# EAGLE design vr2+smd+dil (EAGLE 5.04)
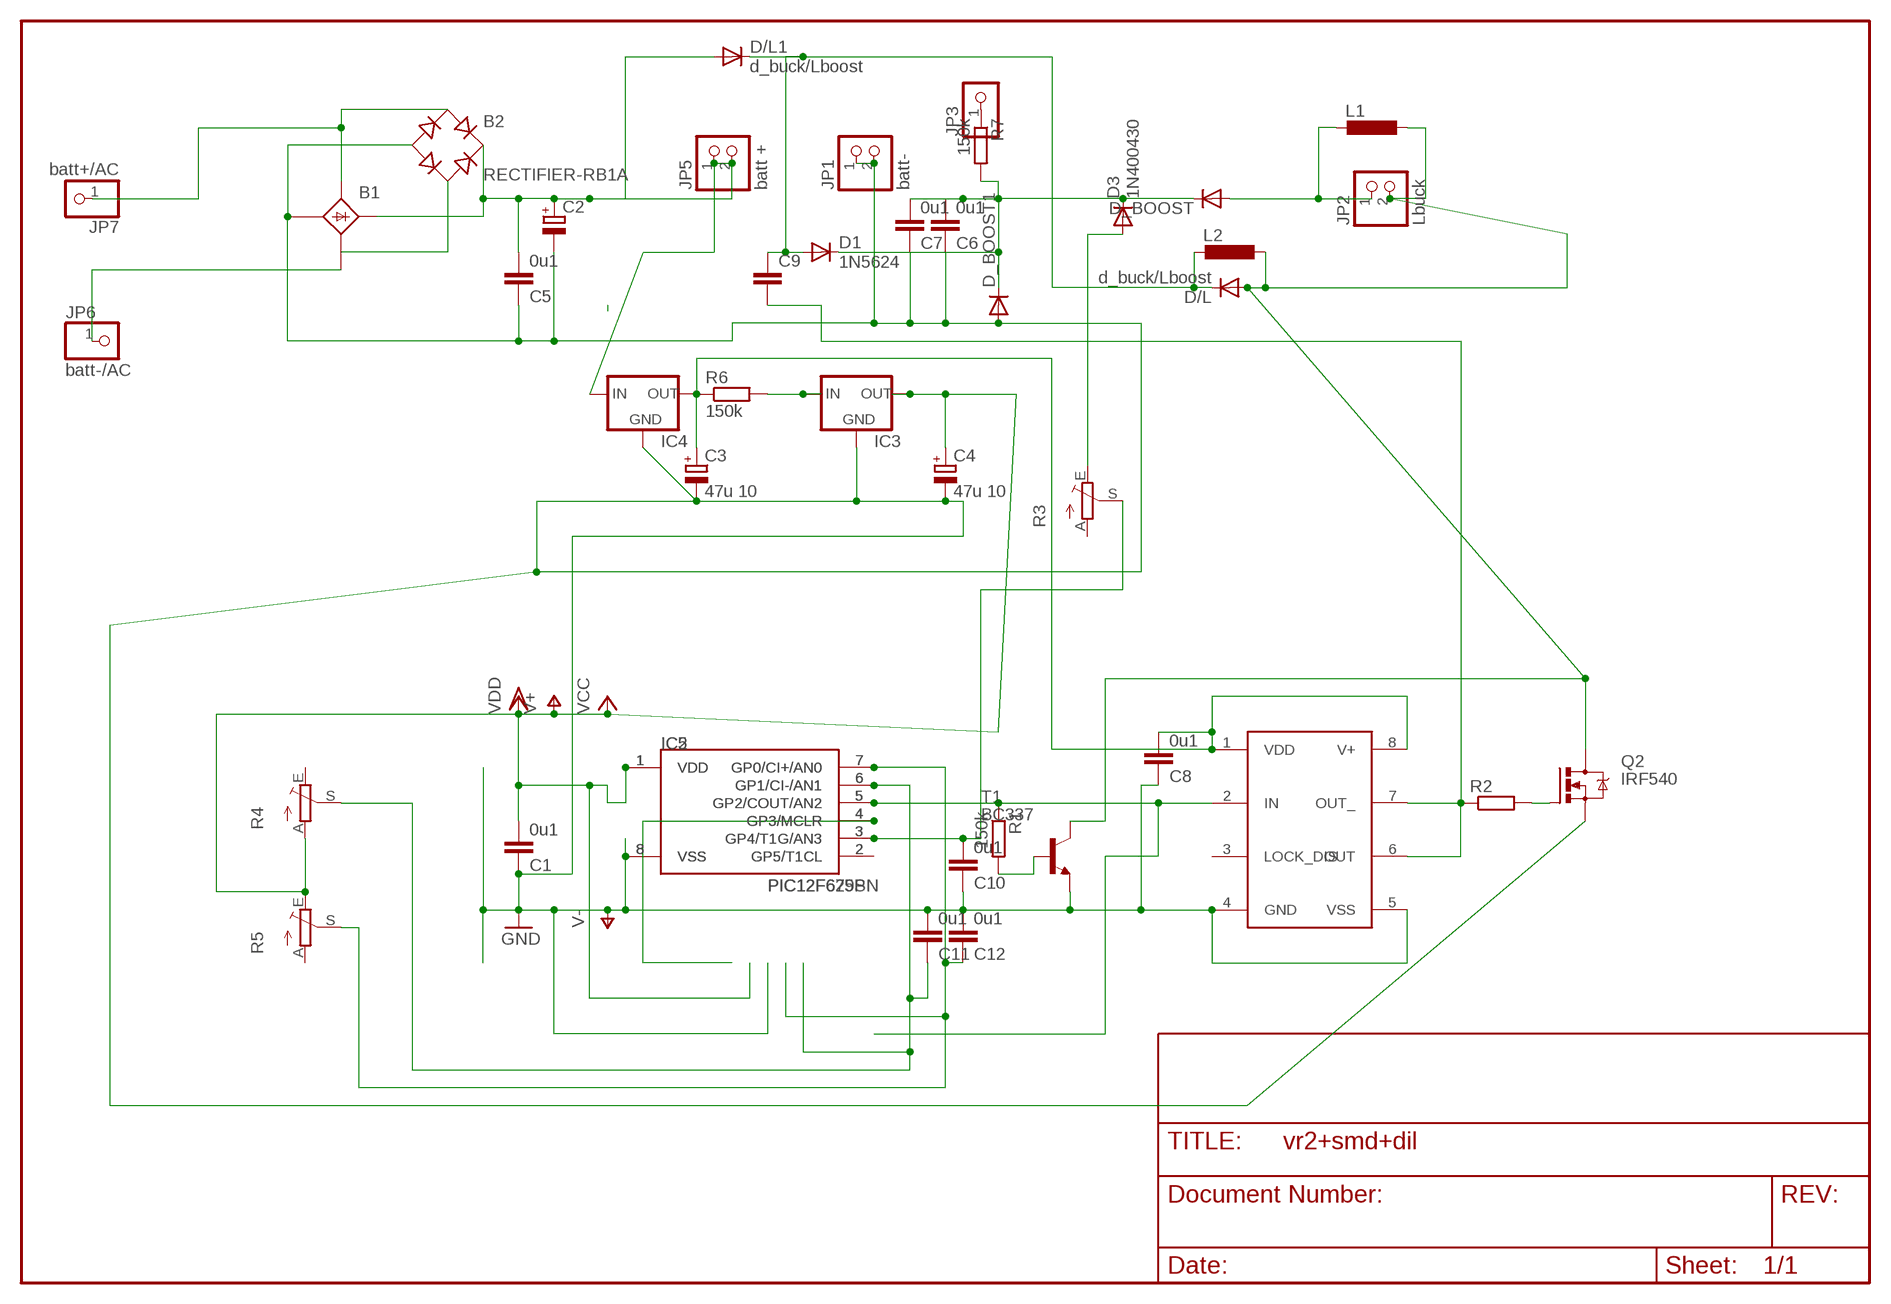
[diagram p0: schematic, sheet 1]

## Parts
B1  B25A-  [B25A-]
B2  RECTIFIER-RB1A  [RB1A]
C1  0u1  C-EUC1206  [C1206]
C2  CPOL-EUE7.5-18  [E7,5-18]
C3  47u 10  CPOL-EUE2,5-6E  [E2,5-6E]
C4  47u 10  CPOL-EUE2.5-6  [E2,5-6]
C5  0u1  C-EUC1206  [C1206]
C6  0u1  C-EUC1206  [C1206]
C7  0u1  C-EUC1206  [C1206]
C8  0u1  C-EUC1206  [C1206]
C9  C-EU050-024X044  [C050-024X044]
C10  0u1  C-EUC1206  [C1206]
C11  0u1  C-EUC1206  [C1206]
C12  0u1  C-EUC1206  [C1206]
D1  1N5624  [DO201-15]
D3  1N400430  [DO41-30]
D/L  d_buck/Lboost  DIODE-C1702-05  [C1702-05]
D/L1  d_buck/Lboost  DIODE-DO201-15  [DO201-15]
D_BOOST  DIODE-DO201-15  [DO201-15]
D_BOOST1  DIODE-DO201-15  [DO201-15]
IC1  TC4432X  [SO-08]
IC2  PIC12F675SN  [SO-08]
IC3  78LXX  [78LXX]
IC4  78LXX  [78LXX]
IC5  PIC12F629P  [DIL8]
JP1  batt-  PINHD-1X2  [1X02]
JP2  Lbuck  PINHD-1X2  [1X02]
JP3  PINHD-1X1  [1X01]
JP5  batt +  PINHD-1X2  [1X02]
JP6  batt-/AC  PINHD-1X1  [1X01]
JP7  batt+/AC  PINHD-1X1  [1X01]
L1  DO3316P  [DO3316P]
L2  DO3316P  [DO3316P]
Q2  IRF540  [TO220BV]
R1  150k  R-EU_0617/17  [0617/17]
R2  R-EU_R1206  [R1206]
R3  TRIM_EU-CA6V  [CA6V]
R4  TRIM_EU-CA6V  [CA6V]
R5  TRIM_EU-CA6V  [CA6V]
R6  150k  R-EU_0204/7  [0204/7]
R7  150k  R-EU_0207/12  [0207/12]
T1  BC337  [TO92]

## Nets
LOAD: C6.2 C7.2 D1.C D3.C D_BOOST1.C D_BOOST.C R7.2
N$1: B1.+ B2.+ C2.+ C5.2 D/L1.A IC4.IN JP5.1 JP5.2
N$2: C9.1 D1.A D/L1.C D/L.C L2.1
N$3: B1.AC2-(AC2) JP6.1
N$4: C3.+ C8.2 IC1.1(VDD) IC1.8(V+) IC4.OUT R6.1
N$5: D_BOOST.A JP2.1 L1.1
N$6: R1.2 T1.2(B)
N$7: C9.2 IC1.6(OUT) IC1.7(OUT_) R2.1
N$8: B1.AC1 B2.AC1 JP7.1
N$9: D/L.A JP2.2 L1.2 L2.2 Q2.D T1.3(C)
N$10: IC2.4(GP3/MCLR) IC5.4(GP3/MCLR)
N$11: B1.AC2 B2.AC2
N$12: C10.2 IC2.3(GP4/T1G/AN3) IC5.3(GP4/T1G/AN3) R3.S
N$13: C12.1 IC2.7(GP0/CI+/AN0) IC5.7(GP0/CI+/AN0) R5.S
N$14: IC1.2(IN) IC2.5(GP2/COUT/AN2) IC5.5(GP2/COUT/AN2) R1.1
N$15: C11.1 IC2.6(GP1/CI-/AN1) IC5.6(GP1/CI-/AN1) R4.S
N$16: D3.A R3.E
N$17: Q2.G R2.2
N$18: IC2.2(GP5/T1CL) IC5.2(GP5/T1CL)
N$19: JP3.1 R7.1
N$20: IC3.IN R6.2
V+: C1.2 C4.+ IC2.1(VDD) IC3.OUT IC5.1(VDD) R4.A R5.E ; supply symbol labelled VCC, VDD
V-: B1.-1(-) B2.- C1.1 C2.- C3.- C4.- C5.1 C6.1 C7.1 C8.1 C10.1 C11.2 C12.2 D_BOOST1.A IC1.4(GND) IC1.5(VSS) IC2.8(VSS) IC3.GND IC4.GND IC5.8(VSS) JP1.1 JP1.2 Q2.S T1.1(E) ; supply symbol labelled GND
Unconnected: B1.+1(+) B1.- B1.AC1-(AC1) IC1.3(LOCK_DIS) R3.A R4.E R5.A

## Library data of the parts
B1 = rectifier:B25A-: RECTIFIER 25-A bridge
B2 = rectifier:RECTIFIER-: Rectifier
C1 C5-C8 C10-C12 = rcl:C-EU: CAPACITOR, European symbol
C2-C4 = rcl:CPOL-EU: POLARIZED CAPACITOR, European symbol
C9 = rcl-2:C-EU: CAPACITOR, European symbol
D1 = diode-1:1N5624: DIODE
D3 = diode-1:1N4004: DIODE
D/L D/L1 D_BOOST D_BOOST1 = diode:DIODE-: DIODE
IC1 = microchip:TC4432
IC2 = microchip-3:PIC12F6*: uPC nW 1k Program Flash memory 2x Timer Comparator 10b A/D converter/ 4xIN
IC3 IC4 = v-reg:78LXX: VOLTAGE REGULATOR
IC5 = microchip-5:PIC12F6*: uPC nW 1k Program Flash memory 2x Timer Comparator 10b A/D converter/ 4xIN
JP1 JP2 JP5 = pinhead:PINHD-1X2: PIN HEADER
JP3 JP6 JP7 = pinhead:PINHD-1X1: PIN HEADER
L1 L2 = inductor-coilcraft:DO3316P: COILCRAFT
Q2 = transistor-power:IRF540: HEXFET Power MOSFET
R1 R6 R7 = rcl:R-EU_: RESISTOR, European symbol
R2 = rcl-2:R-EU_: RESISTOR, European symbol
R3-R5 = pot:TRIM_EU-: POTENTIOMETER
T1 = transistor-neu-to92:BC337: NPN TRANSISTOR

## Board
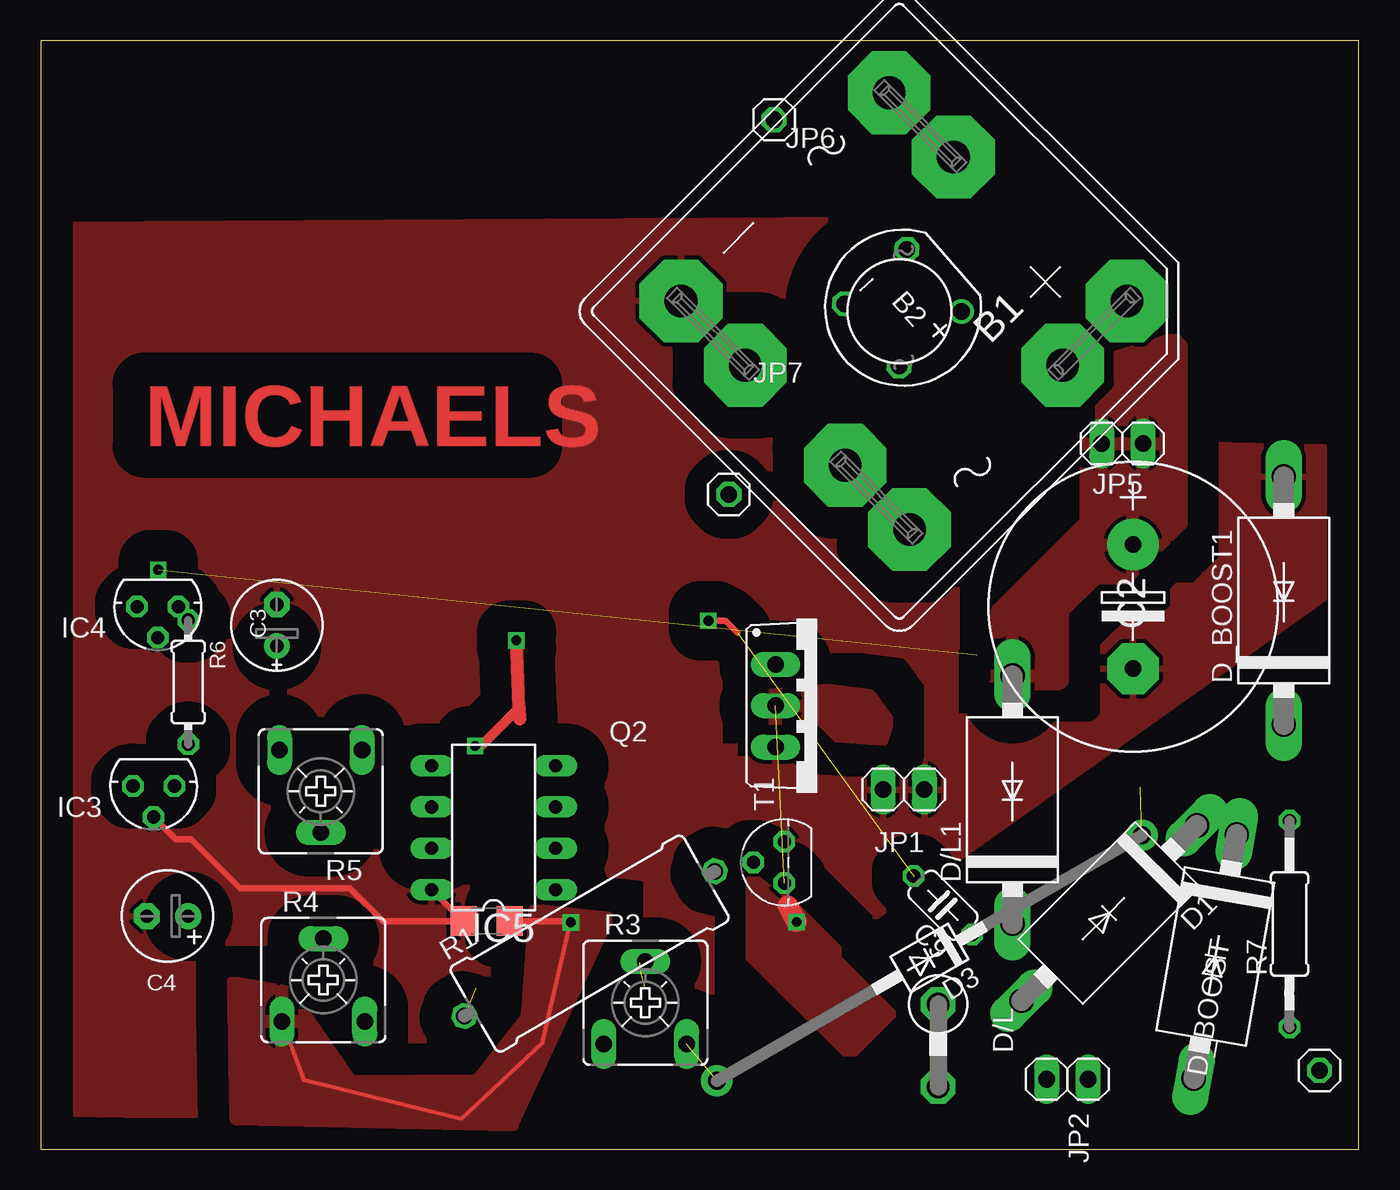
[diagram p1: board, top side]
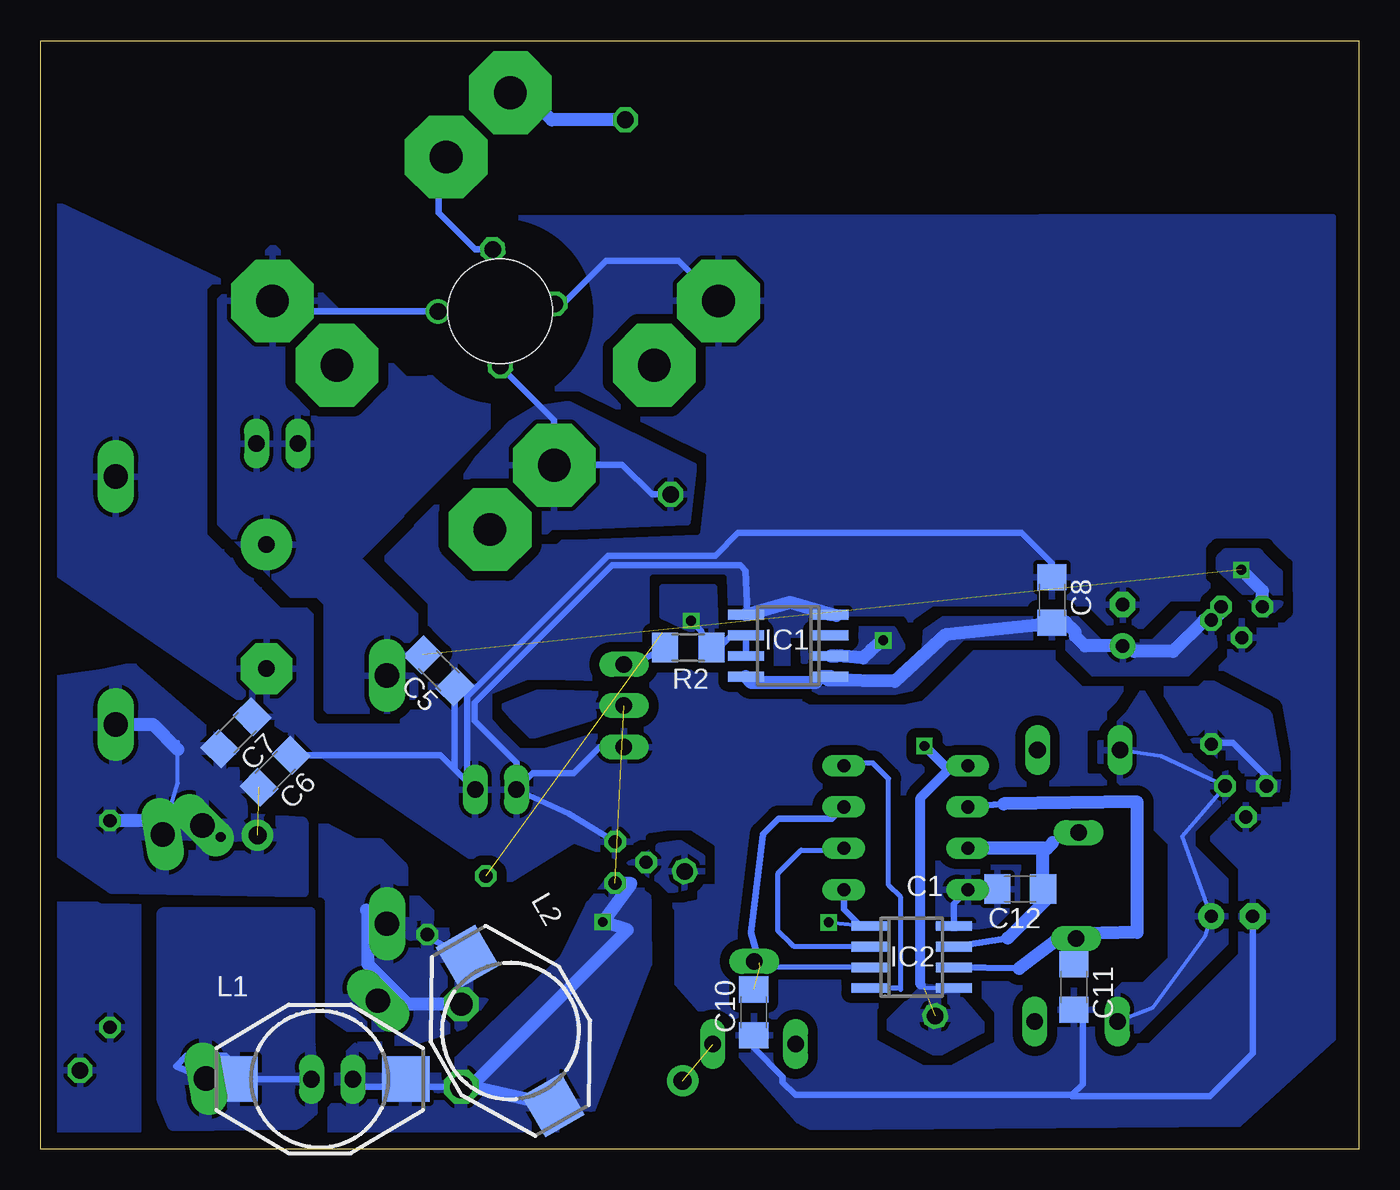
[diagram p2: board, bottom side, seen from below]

Size 81 x 68.09 mm. Coordinates in mm from the lower left corner, seen from the top.
Outline: 0,0 81,0 81,68.09 0,68.09 0,0
Copper layers (1*16): Top 0.035mm / dielectric 1.5mm / Bottom 0.035mm
Design rules "default": minimum track width 10mil, minimum drill 24mil, track to track 8mil, track to pad 8mil, pad to pad 8mil, via to via 8mil, smd to smd 8mil, copper to edge 40mil, drill to drill 8mil, minimum pad ring 10mil, minimum via ring 8mil, stop-mask expansion 4mil, vias tented up to drill 0mil, thermal gap 10mil

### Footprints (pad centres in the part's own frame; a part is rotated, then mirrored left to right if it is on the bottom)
B25A- = drill 2.007 pad 5.08 octagon: + -10.338,9.449; +1 -4.75,9.449; - 9.042,-4.343; -1 9.042,-9.931; AC1 9.042,4.343; AC1- 9.042,9.931; AC2 -9.042,-4.343; AC2- -9.042,-9.931 | hole 6.401: 0,0
RB1A = drill 1.016 round: + -2.54,2.54 | drill 1.016 octagon: - 2.54,-2.54; AC1 2.54,2.54; AC2 -2.54,-2.54
C1206 = smd 1.6 x 1.8: 1 -1.4,0; 2 1.4,0
E7,5-18 = drill 1.016 pad 3.15 round: + -3.81,0 | drill 1.016 pad 3.15 octagon: - 3.81,0
E2,5-6E = drill 0.813 pad 1.575 round: + -1.27,0 | drill 0.813 pad 1.575 octagon: - 1.27,0
E2,5-6 = drill 0.813 pad 1.6 round: + -1.27,0 | drill 0.813 pad 1.6 octagon: - 1.27,0
C050-024X044 = drill 0.813 octagon: 1 -2.54,0; 2 2.54,0
DO201-15 = drill 1.499 long: A 7.62,0; C -7.62,0
DO41-30 = drill 1.118 pad 1.93 round: A 15.08,0; C -15.08,0
C1702-05 = drill 1.397 octagon: A 2.54,0; C -2.54,0
SO-08 = smd 0.6 x 2.2: 1 -1.905,-2.6; 2 -0.635,-2.6; 3 0.635,-2.6; 4 1.905,-2.6; 5 1.905,2.6; 6 0.635,2.6; 7 -0.635,2.6; 8 -1.905,2.6
78LXX = drill 0.813 octagon: GND 0,1.905; IN 1.27,0; OUT -1.27,0
DIL8 = drill 0.813 long: 1 -3.81,-3.81; 2 -1.27,-3.81; 3 1.27,-3.81; 4 3.81,-3.81; 5 3.81,3.81; 6 1.27,3.81; 7 -1.27,3.81; 8 -3.81,3.81
1X02 = drill 1.016 long: 1 -1.27,0; 2 1.27,0
1X01 = drill 1.016 octagon: 1 0,0
DO3316P = smd 2.92 x 2.79: 1 -5.28,0; 2 5.28,0
TO220BV = drill 1.016 long: D 0,-2.54; G -2.54,-2.54; S 2.54,-2.54
0617/17 = drill 1.016 octagon: 1 -8.89,0; 2 8.89,0
R1206 = smd 1.6 x 1.803: 1 -1.422,0; 2 1.422,0
CA6V = drill 1.016 long: A -2.54,-2.54; E 2.54,-2.54; S 0,2.54
0204/7 = drill 0.813 octagon: 1 -3.81,0; 2 3.81,0
0207/12 = drill 0.813 octagon: 1 -6.35,0; 2 6.35,0
TO92 = drill 0.813 octagon: 1 1.27,0; 2 0,1.905; 3 -1.27,0

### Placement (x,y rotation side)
B1  52.76,51.47 225 top
B2  52.99,51.69 221.3 top
C1  27.4,14.01 0 top
C2  67.13,33.32 270 top
C3  14.51,32.18 90 top
C4  7.79,14.31 180 top
C5  56.54,29.38 135 bottom
C6  66.59,23.21 225 bottom
C7  68.99,25.58 225 bottom
C8  18.86,33.73 270 bottom
C9  55.44,14.98 135 top
C10  37.18,8.41 90 bottom
C11  17.51,9.97 270 bottom
C12  20.8,15.98 180 bottom
D1  65.66,14.5 225 top
D3  54.61,11.74 210 top
D/L  55.15,6.36 270 top
D/L1  59.72,21.46 90 top
D_BOOST  72.18,11.83 260 top
D_BOOST1  76.39,33.69 90 top
IC1  35.06,30.92 90 bottom
IC2  27.48,11.8 270 bottom
IC3  6.94,22.3 180 top
IC4  7.2,33.32 180 top
IC5  27.84,19.75 90 top
JP1  53.03,22.09 180 top
JP2  63.09,4.29 180 top
JP3  78.58,4.84 0 top
JP5  66.47,43.35 180 top
JP6  45.07,63.23 0 top
JP7  42.29,40.22 0 top
L1  63.85,4.31 0 bottom
L2  52.14,7.26 300 bottom
Q2  47.7,27.24 270 top
R1  33.73,12.62 30 top
R2  41.21,30.81 180 bottom
R3  37.16,8.99 0 top
R4  17.37,10.39 0 top
R5  17.21,21.98 180 top
R6  9.06,28.69 270 top
R7  76.74,13.83 90 top
T1  45.7,17.61 90 top

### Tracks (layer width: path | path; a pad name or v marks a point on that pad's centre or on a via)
LOAD  (via drill 0.6)  (1 unrouted)
  Bottom 0.254: 72.58,25.02 72.58,24.55 72.58,22.48 D_BOOST.C
  Bottom 0.406: 72.7,20.46 72.83,20.59 | 72.7,20.46 D_BOOST.C | v69.94,19.18 71.29,19.05 72.7,20.46
  Bottom 0.813: D_BOOST1.C 74.1,26.07 72.58,24.55 | D_BOOST.C 72.6,20.34 72.58,20.32 72.72,20.18 R7.2
  pour Bottom (isolate 0.61, rank 2): 68.51,20.29 64.94,20.04 64.93,15.84 76.62,16.07 81.04,19.1 81.04,28.59 77.09,29.13 75.4,29.51 69.44,24.38
N$1  (via drill 0.6)  (1 unrouted)
  Top 0.406: JP5.1 67.92,43.18
  Bottom 0.406: B2.+ 65.28,51.46 66.06,52.23 66.62,52.23 B1.+
  Bottom 0.813: IC4.IN 5.93,34.29 v7.22,35.59
  pour Bottom (isolate 0.61): 5.6,33.03 5.04,33.59 5.04,35.32 6.23,36.51 8.12,36.51 8.44,36.2 8.44,35.8
  pour Bottom (isolate 0.61, rank 2): 53.54,49 53.54,44.32 58.86,39 58.86,38.9 61.71,36.06 61.24,36.06 58,32.82 58,27.88 58.95,26.92 63.33,26.92 63.42,27.01 63.42,33.5 63.98,34.06 65.6,34.06 69.97,38.43 69.97,52.18 66.8,55.36 66.66,55.36 58.58,47.28 57.22,47.28 55.85,48.65 55.85,48.78 55.85,49.06 55.44,49.47
  pour Top (isolate 0.61): 69.62,49.81 70.08,49.35 70.08,38.39 66.76,35.08 64.83,35.08 62.79,33.03 62.79,28.79 62.56,28.56 58.68,28.56 58.8,28.68 58.8,33.13 64.26,38.6 64.26,48.09
N$2
  Bottom 0.406: L2.1 57.24,13.03 C9.1
  Bottom 0.813: D/L.C 58.42,8.9 60.88,11.37 60.88,14.57 60.99,14.68 D/L1.C
  pour Bottom (isolate 0.61, rank 3): 53.36,11.19 53.63,9.65 55,7.75 59.95,6.12 64.45,9.22 64.32,20.07 61.73,18.72 60.22,18.72 58.82,17.32 58.82,16.14 54.73,12.05
N$3
  Bottom 0.813: JP6.1 49.6,63.23 51.95,65.58 51.95,64.49 51.67,64.21 51.69,64.21 52.13,64.66 B1.AC2-
N$4
  Bottom 0.813: IC1.8 37.66,29 37.32,28.66 33.38,28.66 33.03,29.02 IC1.1 32.61,28.8 28.52,28.74 25.41,31.59 18.02,32.37 17.42,31.77 17.42,31.51 16.82,30.91 C3.+ 14.13,30.91 13.8,30.58 11.43,30.58 9.51,32.5 R6.1 8.99,32.44 8.47,32.96 IC4.OUT
  pour Bottom (isolate 0.61, rank 2): 9.15,32.87 10.89,32.87 12.63,31.13 15.88,31.13 17.31,32.55 25.5,32.59 26.62,31.81 26.72,29.86 29.33,29.34 33.51,29.39 33.51,28.28 33.16,28.11 28.5,28.11 27.5,28.31 27.12,28.66 24.34,31.45 18.17,31.45 17.85,31.13 17.85,30.72 16.35,29.22 10.5,29.22 8.84,30.89
N$5
  Bottom 0.406: JP2.1 68.21,4.29 69.64,5.73 72.04,5.73 72.67,5.11 D_BOOST.A
  pour Bottom (isolate 0.61): 64.31,4.23 64.5,6.5 64.5,14.5 73.5,14.45 73.5,3.07 72.84,1.51 65.27,1.6 64.27,2.45
N$6
  pour Bottom (isolate 0.61): 44.8,17.54 43.14,18.44 42.96,18.64 41.72,18.83 40.36,17.96 40.36,16.78 41.39,16.09 42.34,15.88 42.94,16.47
N$7  (via drill 0.6)  (1 unrouted)
  Top 0.406: v41.03,32.46 42.08,32.46 42.82,31.73
  Bottom 0.406: 37.82,30.29 37.87,30.24 | IC1.7 37.82,30.29 | 37.82,30.29 37.66,30.45 IC1.6 38.55,31.56 39.41,30.71 39.92,30.79 R2.1 39.98,30.94 40.42,31.85 v41.03,32.46
  pour Bottom: 40.32,30.59 39.53,32.03 39.63,34.53 42.78,34.53 42.78,32.74 40.32,31.56
N$8
  Bottom 0.406: JP7.1 43.44,40.22 45.27,42.05 49.48,42.05 | 49.48,42.05 50.3,42.05 | 49.48,42.05 B1.AC1 49.44,44.78 B2.AC1
  pour Bottom (isolate 0.61, rank 2): 50.61,45.49 48.56,45.8 40.84,41.99 41.26,38.52 48.03,38.24 49.63,38.24 52.38,35.64 54.98,35.2 56.88,37.11 56.11,39.52 54.12,42.46 52.16,44.55
N$9  (via drill 0.6)  (1 unrouted)
  Top 1.27: v46.45,13.96 45.91,14.96
  Bottom 0.406: 61.98,4.29 61.98,4.46 | 61.98,4.29 JP2.2 | D/L.A 61.98,3.82 61.98,4.29
  Bottom 0.813: 54.58,3.82 D/L.A | 54.58,3.82 44.94,13.46 v46.45,13.96 44.73,16.31 T1.3 | L2.2 54.58,3.82
  pour Bottom (isolate 0.813): 46.03,27.95 50.42,28.07 52.55,27.19 51.75,26.28 50.82,25.35 47.24,26.48 46.39,26.9
  pour Bottom (isolate 0.61, rank 2): 43.86,16.68 46.05,16.33 47.15,14.92 48.73,11.7 56.38,4.33 58.16,4.33 60.02,6.18 61.53,6.18 62.39,5.32 65.74,0.47 65.21,-0.06 48.05,0.51 43.8,11.46
  pour Top: 45.3,15.61 45.79,15.61 49.03,12.37 49.03,11.76 52.44,8.36 52.44,8.24 50.07,5.88 49.36,5.88 43.53,11.71 43.53,16.59 43.76,16.81
  pour Top (isolate 0.61): 44.32,27.65 44.55,27.88 48.31,28.22 50.92,27.88 52.07,26.28 51.72,25.13 48.99,25.36 47.96,26.39 44.21,26.39
N$10
  Bottom 0.305: IC2.4 28.25,9.89 28.15,9.79 28.15,15.47 28.9,16.22 28.9,22.76 29.85,23.71 31.49,23.71 IC5.4
N$11
  Bottom 0.406: B2.AC2 54.32,55.27 56.56,57.52 56.56,60.46 B1.AC2
N$12  (2 unrouted)
  Bottom 0.305: IC2.3 36.79,11.16 R3.S
  Bottom 0.406: 36.84,11.46 37.35,13.28 36.61,19.33 35.66,20.28 32.38,20.28 IC5.3
N$13
  Bottom 0.406: 21.57,12.97 IC2.7 | 19.09,15.43 19.09,15.66 C12.1 | 19.4,18.23 18.8,18.82 18.26,19.37 17.28,19.37 R5.S
  Bottom 0.813: 19.09,15.43 21.57,12.97 | C12.1 19.4,18.23 | IC5.7 19.15,18.48 18.8,18.82
N$14  (via drill 0.6)  (1 unrouted)
  Top 0.61: v26.69,24.77 27.06,24.77 29.41,27.11
  Top 0.813: 29.43,26.42 29.41,27.11 v29.23,31.25
  Bottom 0.254: IC2.5 26.72,9.89 26.93,10.11 | 25.16,23.36 24.23,23.36 IC5.5
  Bottom 0.61: 26.93,10.11 26.93,21.58 25.16,23.36 25.28,23.36 v26.69,24.77
  Bottom 0.813: v29.23,31.25 29.99,30.64 30.46,30.18 32.09,30.3 32.1,30.29 IC1.2
  pour Bottom (isolate 0.61): 30.5,29.44 28.81,29.38 28.06,29.07 28.06,30.98 28.6,31.94 34.19,31.95 34.08,29.95 30.81,29.76
  pour Bottom (isolate 0.61, rank 2): 25.13,9.68 23.25,7.48 25.89,6.05 28.81,7.65 26.67,9.78 26.6,9.78
N$15
  Bottom 0.406: 20.89,11.1 IC2.6 | 21.84,21.21 24.01,21.01 IC5.6 | 17.06,12.93 R4.S 17.37,11.51 C11.1
  Bottom 0.813: 18.14,13.21 13.61,13.32 13.61,21.34 21.84,21.21 | 18.14,13.21 20.89,11.1 | 18.14,13.21 17.06,12.93
N$16  (1 unrouted)
N$17
  Bottom 0.406: Q2.G 45.09,29.78 44.9,29.59 R2.2
N$18
  Bottom 0.305: IC2.2 34.71,12.43 34.88,12.61 34.9,12.61 35.68,13.4 35.68,16.95 34.27,18.36 31.76,18.36 IC5.2
N$19
  pour Bottom (isolate 0.61, rank 3): 75,1.13 81.01,1.22 81.24,3.64 81.24,11.06 80,15 78,15 75,15.05
N$20
  Bottom 0.406: IC3.IN 5.67,22.9 7.73,24.96 8.99,24.96 R6.2
  pour Bottom (isolate 0.61, rank 3): 10.4,25.27 11.9,28.33 9.06,28.42 5.72,26.68 5.09,23.25 5.25,22.02 6.21,22.02
V+  (via drill 0.6)
  Top 0.254: R4.A 16.19,4.25 25.87,1.87 30.83,6.53 v32.57,13.93
  Top 0.406: C1.2 32.5,14.01 v32.57,13.93
  Bottom 0.254: v32.57,13.93 IC2.1 | R4.A 12.63,8.72 9.45,13.08 C4.+ 10.86,19.21 IC3.OUT 12.12,24.13 R5.E
  Bottom 0.406: IC2.1 30.6,13.7 31.64,14.74 IC5.1
  pour Bottom (isolate 0.61): 14.35,6.87 13.97,6.87 8.2,12.64 8.2,16.55 10.23,18.58 10.23,19.57 7.82,21.98 7.82,23.14 8.76,22.9 9.34,23.19 10.28,24.13 10.89,24.13 13.31,28.05 14.13,26.77 15.9,25.01 15.9,23.8 13.8,21.7 13.8,21.04 11.55,18.8 11.55,11.71 13.2,10.06 14.51,10.06 15.83,8.74
  pour Top (isolate 0.61, rank 2): 11.82,10.22 11.99,1.87 28.98,1.49 34.86,14.19 30.35,14.68 29.89,8.13 26.82,4.19 19.08,4.13 15.29,9.61
V-
  Top 0.406: IC3.GND 8.29,19.05 9.24,19.05 12.25,16.04 19,16.04 21.03,14.01 C1.1 25.96,14.01 IC5.8
  Bottom 0.406: B2.- 48.9,51.92 46.26,54.56 41.8,54.56 B1.-1 | C6.1 56.42,24.2 54.82,22.6 | C5.1 55.55,23.33 54.82,22.6 | 54.82,22.6 JP1.1 | JP1.2 51.76,23.75 54.34,26.33 54.34,27.41 45.88,35.87 38.01,35.87 37.68,35.53 37.58,32.91 IC1.5 | JP1.2 51.45,21.78 | T1.1 48.52,20.6 JP1.2 | Q2.S 46.64,24.7 48.26,23.09 50.76,23.09 JP1.2 | C8.1 18.86,35.98 20.74,37.86 38.15,37.86 39.54,36.46 46.15,36.46 54.81,27.8 54.81,22.61 54.82,22.6 | IC2.8 24.88,15.08 IC5.8 23.98,15.98 C12.2 | C10.1 37.18,6.24 35.4,4.46 35.4,4.1 34.63,3.33 17.73,3.33 | 17.73,3.33 17.64,3.33 16.96,4 16.96,8.02 C11.2 | C4.- 6.52,5.88 9.17,3.24 17.64,3.24 17.73,3.33
  Bottom 0.813: 34.96,33.59 IC1.4 | IC1.5 34.96,33.59 | 34.96,33.59 32.11,32.78
  pour Bottom (isolate 0.61, rank 4): 1.6,57.29 1.6,6.79 7.34,1.55 33.66,1.36 34.45,1.78 41.87,10.15 41.87,14.69 43.66,17.21 48.23,18.97 52.35,16.43 80.77,35.9 80.77,44.59 81.1,58.56 48.45,43.12 55.83,57.18
  pour Top (isolate 1.93, rank 3): 1.46,56.78 55.48,57.12 49.34,44.32 61.64,36.68 70.3,43.29 81.71,43.07 80.79,35.19 33.49,1.6 1.79,2.17

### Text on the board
Top: MICHAELS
